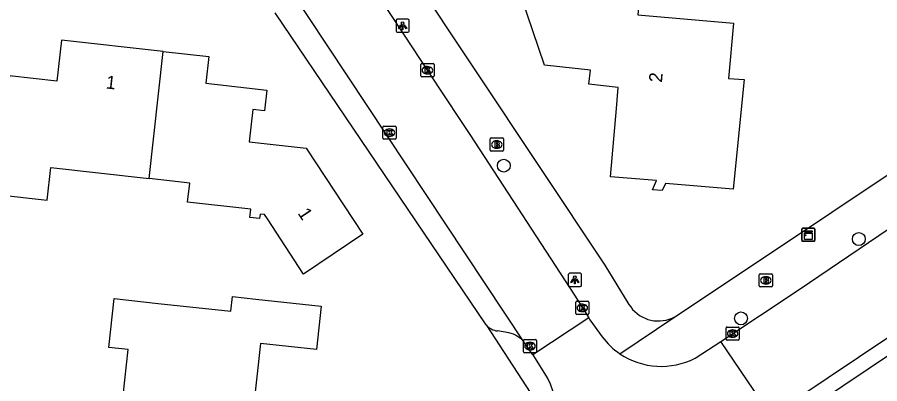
# Model space of a CAD drawing. Extents: x 162398 to 163643, y 386453 to 387397.
# Drawn here: x 163055.2 to 163120.8, y 386794.5 to 386822.3 of the extents above; entities that cross this region are included whole.
import ezdxf

# ---------------------------------------------------------------- set-up
doc = ezdxf.new("R2010")
doc.units = 0
for name, color, linetype in [('IMGEO_Boom', 7, 'Continuous'), ('IMGEO_Brandkraan', 7, 'Continuous'), ('IMGEO_Kast', 7, 'Continuous'), ('IMGEO_Kolk', 7, 'Continuous'), ('IMGEO_Lichtpunt', 7, 'Continuous'), ('IMGEO_Pand', 7, 'Continuous'), ('IMGEO_Pand_nummerreeks', 7, 'Continuous'), ('IMGEO_Parkeervlak_open', 7, 'Continuous'), ('IMGEO_Rijbaan_lokaal_gesloten', 7, 'Continuous'), ('IMGEO_Rijbaan_lokaal_open', 7, 'Continuous'), ('IMGEO_Voetpad_open', 7, 'Continuous')]:
    doc.layers.add(name, color=color, linetype=linetype)

msp = doc.modelspace()

# ---------------------------------------------------------------- linework, layer by layer
at = {"layer": 'IMGEO_Boom'}
for centre in [(163092.224, 386811.045), (163119.219, 386805.465), (163110.256, 386799.441)]:
    msp.add_circle(centre, 0.489, dxfattribs=at)
at = {"layer": 'IMGEO_Brandkraan'}
for p, q in [((163091.19, 386812.221), (163091.19, 386813.073)), ((163091.265, 386813.147), (163092.117, 386813.147)), ((163091.678, 386812.927), (163091.703, 386812.927)), ((163092.191, 386813.073), (163092.191, 386812.221)), ((163092.117, 386812.147), (163091.265, 386812.147)), ((163091.701, 386812.367), (163091.676, 386812.367)), ((163111.652, 386801.906), (163111.652, 386802.758)), ((163111.727, 386802.832), (163112.579, 386802.832)), ((163112.14, 386802.612), (163112.165, 386802.612)), ((163112.653, 386802.758), (163112.653, 386801.906)), ((163112.579, 386801.832), (163111.727, 386801.832)), ((163112.163, 386802.052), (163112.138, 386802.052))]:
    msp.add_line(p, q, dxfattribs=at)
for points in [[(163091.19, 386812.221), (163091.19, 386813.073)], [(163091.265, 386813.147), (163092.117, 386813.147)], [(163091.538, 386812.847), (163091.538, 386812.447), (163091.751, 386812.447)], [(163091.769, 386812.847), (163091.538, 386812.847)], [(163092.191, 386813.073), (163092.191, 386812.221)], [(163092.117, 386812.147), (163091.265, 386812.147)], [(163091.717, 386812.766), (163091.663, 386812.766), (163091.663, 386812.69)], [(163091.663, 386812.69), (163091.716, 386812.69)], [(163091.725, 386812.614), (163091.663, 386812.614), (163091.663, 386812.533)], [(163091.663, 386812.533), (163091.725, 386812.533)], [(163111.652, 386801.906), (163111.652, 386802.758)], [(163111.727, 386802.832), (163112.579, 386802.832)], [(163112, 386802.532), (163112, 386802.132), (163112.213, 386802.132)], [(163112.231, 386802.532), (163112, 386802.532)], [(163112.179, 386802.451), (163112.125, 386802.451), (163112.125, 386802.375)], [(163112.125, 386802.375), (163112.178, 386802.375)], [(163112.653, 386802.758), (163112.653, 386801.906)], [(163112.579, 386801.832), (163111.727, 386801.832)], [(163112.187, 386802.299), (163112.125, 386802.299), (163112.125, 386802.218)], [(163112.125, 386802.218), (163112.187, 386802.218)]]:
    msp.add_lwpolyline(points, dxfattribs=at)
for centre, radius, start, end in [((163091.267, 386813.071), 0.0765, 91.55205, 178.44795), ((163091.267, 386813.071), 0.0765, 91.55205, 178.44795), ((163091.773, 386812.702), 0.145, 59.4692, 91.53667), ((163091.798, 386812.749), 0.0922, 285.51372, 58.15012), ((163092.115, 386813.071), 0.0765, 1.55205, 88.44795), ((163092.115, 386813.071), 0.0765, 1.55205, 88.44795), ((163091.267, 386812.223), 0.0765, 181.55205, 268.44795), ((163091.267, 386812.223), 0.0765, 181.55205, 268.44795), ((163091.718, 386812.728), 0.0379, 267.82845, 90.93552), ((163091.726, 386812.573), 0.0404, 269.87594, 90.50774), ((163091.757, 386812.698), 0.251, 268.66757, 293.53466), ((163091.803, 386812.557), 0.105, 301.31148, 78.98903), ((163092.115, 386812.223), 0.0765, 271.55205, 358.44795), ((163092.115, 386812.223), 0.0765, 271.55205, 358.44795), ((163111.729, 386802.756), 0.0765, 91.55205, 178.44795), ((163111.729, 386802.756), 0.0765, 91.55205, 178.44795), ((163112.18, 386802.413), 0.0379, 267.82845, 90.93552), ((163112.235, 386802.387), 0.145, 59.4692, 91.53667), ((163112.26, 386802.434), 0.0922, 285.51372, 58.15012), ((163112.265, 386802.242), 0.105, 301.31148, 78.98903), ((163112.577, 386802.756), 0.0765, 1.55205, 88.44795), ((163112.577, 386802.756), 0.0765, 1.55205, 88.44795), ((163111.729, 386801.908), 0.0765, 181.55205, 268.44795), ((163111.729, 386801.908), 0.0765, 181.55205, 268.44795), ((163112.188, 386802.258), 0.0404, 269.87594, 90.50774), ((163112.219, 386802.383), 0.251, 268.66757, 293.53466), ((163112.577, 386801.908), 0.0765, 271.55205, 358.44795), ((163112.577, 386801.908), 0.0765, 271.55205, 358.44795)]:
    msp.add_arc(centre, radius, start, end, dxfattribs=at)
for centre, major_axis, ratio, start_param, end_param in [((163091.677, 386812.647), (-0.387, 0.002), 0.722429, 4.712389, 7.853982), ((163091.702, 386812.647), (-0.39, 0.002), 0.717154, 1.570796, 4.712389), ((163112.139, 386802.332), (-0.387, 0.002), 0.722429, 4.712389, 7.853982), ((163112.164, 386802.332), (-0.39, 0.002), 0.717154, 1.570796, 4.712389)]:
    msp.add_ellipse(centre, major_axis=major_axis, ratio=ratio, start_param=start_param, end_param=end_param, dxfattribs=at)
at = {"layer": 'IMGEO_Kast'}
for p, q in [((163114.961, 386806.297), (163115.802, 386806.297)), ((163115.802, 386806.297), (163114.961, 386806.297)), ((163114.886, 386805.372), (163114.886, 386806.213)), ((163114.886, 386806.213), (163114.886, 386805.372)), ((163115.886, 386806.222), (163115.886, 386805.381)), ((163115.886, 386805.381), (163115.886, 386806.222)), ((163115.811, 386805.297), (163114.97, 386805.297)), ((163114.97, 386805.297), (163115.811, 386805.297))]:
    msp.add_line(p, q, dxfattribs=at)
for points in [[(163115.081, 386806.087), (163115.681, 386806.087), (163115.681, 386806.002), (163115.081, 386806.002), (163115.081, 386806.087)], [(163115.081, 386805.912), (163115.681, 386805.912), (163115.681, 386805.423), (163115.081, 386805.423), (163115.081, 386805.912)]]:
    msp.add_lwpolyline(points, dxfattribs=at)
msp.add_circle((163115.165, 386805.761), 0.0377, dxfattribs=at)
for centre, start, end in [((163114.964, 386806.219), 92.4484, 184.28452), ((163114.964, 386806.219), 92.4484, 184.28452), ((163115.808, 386806.219), 2.4484, 94.28452), ((163115.808, 386806.219), 2.4484, 94.28452), ((163114.964, 386805.375), 182.4484, 274.28452), ((163114.964, 386805.375), 182.4484, 274.28452), ((163115.808, 386805.375), 272.4484, 4.28452), ((163115.808, 386805.375), 272.4484, 4.28452)]:
    msp.add_arc(centre, 0.0779, start, end, dxfattribs=at)
at = {"layer": 'IMGEO_Kolk'}
for p, q in [((163085.917, 386817.864), (163085.917, 386818.716)), ((163085.992, 386818.79), (163086.844, 386818.79)), ((163086.918, 386818.716), (163086.918, 386817.864)), ((163086.405, 386818.57), (163086.43, 386818.57)), ((163086.844, 386817.79), (163085.992, 386817.79)), ((163086.428, 386818.01), (163086.403, 386818.01)), ((163083.033, 386813.123), (163083.033, 386813.975)), ((163083.108, 386814.049), (163083.96, 386814.049)), ((163083.521, 386813.829), (163083.546, 386813.829)), ((163084.034, 386813.975), (163084.034, 386813.123)), ((163083.96, 386813.049), (163083.108, 386813.049)), ((163083.544, 386813.269), (163083.519, 386813.269)), ((163097.698, 386799.816), (163097.698, 386800.668)), ((163097.773, 386800.742), (163098.625, 386800.742)), ((163098.186, 386800.522), (163098.211, 386800.522)), ((163098.699, 386800.668), (163098.699, 386799.816)), ((163098.625, 386799.742), (163097.773, 386799.742)), ((163098.209, 386799.962), (163098.184, 386799.962)), ((163109.123, 386797.862), (163109.123, 386798.714)), ((163109.198, 386798.788), (163110.05, 386798.788)), ((163109.611, 386798.568), (163109.636, 386798.568)), ((163110.124, 386798.714), (163110.124, 386797.862)), ((163093.718, 386796.911), (163093.718, 386797.763)), ((163093.793, 386797.837), (163094.645, 386797.837)), ((163094.719, 386797.763), (163094.719, 386796.911)), ((163110.05, 386797.788), (163109.198, 386797.788)), ((163109.634, 386798.008), (163109.609, 386798.008)), ((163094.206, 386797.617), (163094.231, 386797.617)), ((163094.645, 386796.837), (163093.793, 386796.837)), ((163094.229, 386797.057), (163094.204, 386797.057))]:
    msp.add_line(p, q, dxfattribs=at)
for points in [[(163085.917, 386817.864), (163085.917, 386818.716)], [(163085.992, 386818.79), (163086.844, 386818.79)], [(163086.918, 386818.716), (163086.918, 386817.864)], [(163086.238, 386818.49), (163086.361, 386818.49), (163086.361, 386818.339), (163086.491, 386818.49), (163086.655, 386818.49), (163086.509, 386818.339), (163086.662, 386818.09), (163086.51, 386818.09), (163086.425, 386818.254), (163086.361, 386818.187), (163086.361, 386818.09), (163086.238, 386818.09), (163086.238, 386818.49)], [(163086.844, 386817.79), (163085.992, 386817.79)], [(163083.033, 386813.123), (163083.033, 386813.975)], [(163083.108, 386814.049), (163083.96, 386814.049)], [(163083.354, 386813.749), (163083.477, 386813.749), (163083.477, 386813.598), (163083.607, 386813.749), (163083.771, 386813.749), (163083.625, 386813.598), (163083.778, 386813.349), (163083.626, 386813.349), (163083.541, 386813.513), (163083.477, 386813.446), (163083.477, 386813.349), (163083.354, 386813.349), (163083.354, 386813.749)], [(163084.034, 386813.975), (163084.034, 386813.123)], [(163083.96, 386813.049), (163083.108, 386813.049)], [(163097.698, 386799.816), (163097.698, 386800.668)], [(163097.773, 386800.742), (163098.625, 386800.742)], [(163098.019, 386800.442), (163098.142, 386800.442), (163098.142, 386800.291), (163098.272, 386800.442), (163098.436, 386800.442), (163098.29, 386800.291), (163098.443, 386800.042), (163098.291, 386800.042), (163098.206, 386800.206), (163098.142, 386800.139), (163098.142, 386800.042), (163098.019, 386800.042), (163098.019, 386800.442)], [(163098.699, 386800.668), (163098.699, 386799.816)], [(163098.625, 386799.742), (163097.773, 386799.742)], [(163109.123, 386797.862), (163109.123, 386798.714)], [(163109.198, 386798.788), (163110.05, 386798.788)], [(163109.444, 386798.488), (163109.567, 386798.488), (163109.567, 386798.337), (163109.697, 386798.488), (163109.861, 386798.488), (163109.715, 386798.337), (163109.868, 386798.088), (163109.716, 386798.088), (163109.631, 386798.252), (163109.567, 386798.185), (163109.567, 386798.088), (163109.444, 386798.088), (163109.444, 386798.488)], [(163110.124, 386798.714), (163110.124, 386797.862)], [(163093.718, 386796.911), (163093.718, 386797.763)], [(163093.793, 386797.837), (163094.645, 386797.837)], [(163094.719, 386797.763), (163094.719, 386796.911)], [(163110.05, 386797.788), (163109.198, 386797.788)], [(163094.039, 386797.537), (163094.162, 386797.537), (163094.162, 386797.386), (163094.292, 386797.537), (163094.456, 386797.537), (163094.31, 386797.386), (163094.463, 386797.137), (163094.311, 386797.137), (163094.226, 386797.301), (163094.162, 386797.234), (163094.162, 386797.137), (163094.039, 386797.137), (163094.039, 386797.537)], [(163094.645, 386796.837), (163093.793, 386796.837)]]:
    msp.add_lwpolyline(points, dxfattribs=at)
for centre, start, end in [((163085.994, 386818.714), 91.55205, 178.44795), ((163085.994, 386818.714), 91.55205, 178.44795), ((163086.842, 386818.714), 1.55205, 88.44795), ((163086.842, 386818.714), 1.55205, 88.44795), ((163085.994, 386817.866), 181.55205, 268.44795), ((163085.994, 386817.866), 181.55205, 268.44795), ((163086.842, 386817.866), 271.55205, 358.44795), ((163086.842, 386817.866), 271.55205, 358.44795), ((163083.11, 386813.973), 91.55205, 178.44795), ((163083.11, 386813.973), 91.55205, 178.44795), ((163083.958, 386813.973), 1.55205, 88.44795), ((163083.958, 386813.973), 1.55205, 88.44795), ((163083.11, 386813.125), 181.55205, 268.44795), ((163083.11, 386813.125), 181.55205, 268.44795), ((163083.958, 386813.125), 271.55205, 358.44795), ((163083.958, 386813.125), 271.55205, 358.44795), ((163097.775, 386800.666), 91.55205, 178.44795), ((163097.775, 386800.666), 91.55205, 178.44795), ((163098.623, 386800.666), 1.55205, 88.44795), ((163098.623, 386800.666), 1.55205, 88.44795), ((163097.775, 386799.818), 181.55205, 268.44795), ((163097.775, 386799.818), 181.55205, 268.44795), ((163098.623, 386799.818), 271.55205, 358.44795), ((163098.623, 386799.818), 271.55205, 358.44795), ((163109.2, 386798.712), 91.55205, 178.44795), ((163109.2, 386798.712), 91.55205, 178.44795), ((163110.048, 386798.712), 1.55205, 88.44795), ((163110.048, 386798.712), 1.55205, 88.44795), ((163093.795, 386797.761), 91.55205, 178.44795), ((163093.795, 386797.761), 91.55205, 178.44795), ((163094.643, 386797.761), 1.55205, 88.44795), ((163094.643, 386797.761), 1.55205, 88.44795), ((163109.2, 386797.864), 181.55205, 268.44795), ((163109.2, 386797.864), 181.55205, 268.44795), ((163110.048, 386797.864), 271.55205, 358.44795), ((163110.048, 386797.864), 271.55205, 358.44795), ((163093.795, 386796.913), 181.55205, 268.44795), ((163093.795, 386796.913), 181.55205, 268.44795), ((163094.643, 386796.913), 271.55205, 358.44795), ((163094.643, 386796.913), 271.55205, 358.44795)]:
    msp.add_arc(centre, 0.0765, start, end, dxfattribs=at)
for centre, major_axis, ratio, start_param, end_param in [((163086.404, 386818.29), (-0.387, 0.002), 0.722429, 4.712389, 7.853982), ((163086.429, 386818.29), (-0.39, 0.002), 0.717154, 1.570796, 4.712389), ((163083.52, 386813.549), (-0.387, 0.002), 0.722429, 4.712389, 7.853982), ((163083.545, 386813.549), (-0.39, 0.002), 0.717154, 1.570796, 4.712389), ((163098.185, 386800.242), (-0.387, 0.002), 0.722429, 4.712389, 7.853982), ((163098.21, 386800.242), (-0.39, 0.002), 0.717154, 1.570796, 4.712389), ((163109.61, 386798.288), (-0.387, 0.002), 0.722429, 4.712389, 7.853982), ((163109.635, 386798.288), (-0.39, 0.002), 0.717154, 1.570796, 4.712389), ((163094.205, 386797.337), (-0.387, 0.002), 0.722429, 4.712389, 7.853982), ((163094.23, 386797.337), (-0.39, 0.002), 0.717154, 1.570796, 4.712389)]:
    msp.add_ellipse(centre, major_axis=major_axis, ratio=ratio, start_param=start_param, end_param=end_param, dxfattribs=at)
at = {"layer": 'IMGEO_Lichtpunt'}
for p, q in [((163084.031, 386822.069), (163084.031, 386821.262)), ((163084.031, 386822.069), (163084.031, 386821.262)), ((163084.933, 386822.164), (163084.125, 386822.164)), ((163084.933, 386822.164), (163084.125, 386822.164)), ((163085.027, 386821.262), (163085.027, 386822.069)), ((163085.027, 386821.262), (163085.027, 386822.069)), ((163084.125, 386821.168), (163084.933, 386821.168)), ((163084.125, 386821.168), (163084.933, 386821.168)), ((163097.131, 386802.773), (163097.131, 386801.966)), ((163097.131, 386802.773), (163097.131, 386801.966)), ((163098.033, 386802.868), (163097.225, 386802.868)), ((163098.033, 386802.868), (163097.225, 386802.868)), ((163098.127, 386801.966), (163098.127, 386802.773)), ((163098.127, 386801.966), (163098.127, 386802.773)), ((163097.225, 386801.872), (163098.033, 386801.872)), ((163097.225, 386801.872), (163098.033, 386801.872))]:
    msp.add_line(p, q, dxfattribs=at)
for points in [[(163084.405, 386821.733), (163084.444, 386821.705), (163084.256, 386821.443), (163084.218, 386821.47), (163084.405, 386821.733)], [(163084.507, 386821.685), (163084.554, 386821.685), (163084.554, 386821.363), (163084.507, 386821.363), (163084.507, 386821.685)], [(163084.617, 386821.705), (163084.655, 386821.732), (163084.842, 386821.47), (163084.803, 386821.442), (163084.617, 386821.705)], [(163097.505, 386802.437), (163097.544, 386802.409), (163097.356, 386802.147), (163097.318, 386802.174), (163097.505, 386802.437)], [(163097.607, 386802.389), (163097.654, 386802.389), (163097.654, 386802.067), (163097.607, 386802.067), (163097.607, 386802.389)], [(163097.717, 386802.409), (163097.755, 386802.436), (163097.942, 386802.174), (163097.903, 386802.146), (163097.717, 386802.409)]]:
    msp.add_lwpolyline(points, dxfattribs=at)
for centre in [(163084.53, 386821.867), (163097.63, 386802.571)]:
    msp.add_circle(centre, 0.0994, dxfattribs=at)
for centre, start, end in [((163084.125, 386822.069), 90, 180), ((163084.125, 386822.069), 90, 180), ((163084.933, 386822.069), 0, 90), ((163084.933, 386822.069), 0, 90), ((163084.125, 386821.262), 180, 270), ((163084.125, 386821.262), 180, 270), ((163084.933, 386821.262), 270, 0), ((163084.933, 386821.262), 270, 360), ((163097.225, 386802.773), 90, 180), ((163097.225, 386802.773), 90, 180), ((163098.033, 386802.773), 0, 90), ((163098.033, 386802.773), 0, 90), ((163097.225, 386801.966), 180, 270), ((163097.225, 386801.966), 180, 270), ((163098.033, 386801.966), 270, 0), ((163098.033, 386801.966), 270, 360)]:
    msp.add_arc(centre, 0.0946, start, end, dxfattribs=at)
at = {"layer": 'IMGEO_Pand'}
for points in [[(163101.8, 386825.576), (163102.676, 386825.5), (163102.414, 386822.492), (163109.685, 386821.858), (163109.32, 386817.672), (163110.501, 386817.598), (163109.668, 386809.251), (163104.521, 386809.7), (163104.262, 386809.153), (163103.522, 386809.218), (163103.835, 386809.928), (163100.333, 386810.201), (163100.785, 386815.382), (163100.923, 386816.971), (163098.696, 386817.239), (163098.807, 386818.304), (163095.318, 386818.67), (163092.713, 386826.368), (163098.293, 386825.882)], [(163066.327, 386819.722), (163058.593, 386820.582), (163058.245, 386817.455), (163054.632, 386817.856), (163054.132, 386813.363), (163053.632, 386808.864), (163057.516, 386808.432), (163057.789, 386810.893), (163065.254, 386810.063)], [(163065.254, 386810.063), (163066.327, 386819.722)], [(163066.327, 386819.722), (163069.802, 386819.335), (163069.575, 386817.3), (163074.213, 386816.784), (163074.037, 386815.205), (163073.141, 386815.305), (163072.867, 386812.843), (163077.194, 386812.362), (163081.496, 386805.85), (163076.99, 386802.809), (163074.251, 386806.993), (163074.029, 386807.331), (163073.692, 386807.369), (163073.654, 386807.022), (163072.91, 386807.104), (163072.981, 386807.748), (163068.183, 386808.281), (163068.343, 386809.719), (163065.254, 386810.063)], [(163062.9, 386790.106), (163063.658, 386797.073), (163062.183, 386797.234), (163062.587, 386800.949), (163065.941, 386800.584), (163071.468, 386799.982), (163071.59, 386801.104), (163073.363, 386800.911), (163078.333, 386800.37), (163077.975, 386797.081), (163073.726, 386797.543), (163072.8, 386789.031)]]:
    msp.add_lwpolyline(points, dxfattribs=at)
at = {"layer": 'IMGEO_Parkeervlak_open'}
msp.add_lwpolyline([(163090.874, 386798.95), (163074.837, 386822.643)], dxfattribs=at)
at = {"layer": 'IMGEO_Rijbaan_lokaal_gesloten'}
for points in [[(163108.718, 386797.688), (163114.688, 386801.643), (163126.014, 386809.308), (163142.367, 386820.061), (163142.553, 386820.191)], [(163128.699, 386802.855), (163128.182, 386802.509), (163114.647, 386793.426), (163112.536, 386792.008)]]:
    msp.add_lwpolyline(points, dxfattribs=at)
at = {"layer": 'IMGEO_Rijbaan_lokaal_open'}
for points in [[(163045.549, 386876.981), (163048.719, 386873.794), (163051.94, 386869.963), (163054.925, 386865.823), (163055.939, 386864.293), (163058.066, 386861.082), (163070.601, 386842.162), (163072.682, 386839.022), (163084.661, 386820.941), (163086.459, 386818.227), (163088.943, 386814.478), (163089.654, 386813.404), (163097.59, 386801.208), (163098.684, 386799.487)], [(163093.805, 386797.593), (163074.36, 386826.913)], [(163098.684, 386799.487), (163094.437, 386796.681)], [(163098.684, 386799.487), (163098.774, 386799.346), (163099.704, 386798.039)], [(163094.437, 386796.681), (163093.805, 386797.593)], [(163106.767, 386796.421), (163108.718, 386797.688)], [(163111.717, 386793.28), (163108.718, 386797.688)], [(163095.547, 386794.922), (163094.499, 386796.592), (163094.437, 386796.681)]]:
    msp.add_lwpolyline(points, dxfattribs=at)
for centre, radius, start, end in [((163104.198, 386801.429), 5.629, 217.0304, 236.06121), ((163104.198, 386801.432), 5.631, 236.08046, 297.14664), ((163090.757, 386792.349), 5.437, 301.52199, 28.24641)]:
    msp.add_arc(centre, radius, start, end, dxfattribs=at)
at = {"layer": 'IMGEO_Voetpad_open'}
for points in [[(163055.371, 386870.345), (163099.918, 386803.497), (163101.741, 386800.505), (163101.872, 386800.31), (163102.019, 386800.128), (163102.182, 386799.96), (163102.36, 386799.807), (163102.551, 386799.671), (163102.753, 386799.552), (163102.964, 386799.452), (163103.184, 386799.371), (163103.411, 386799.309), (163103.641, 386799.269), (163103.875, 386799.249), (163104.109, 386799.25), (163104.343, 386799.272), (163104.573, 386799.315), (163104.799, 386799.378), (163105.018, 386799.461), (163105.229, 386799.564)], [(163105.229, 386799.564), (163105.43, 386799.684), (163105.441, 386799.692), (163140.645, 386823.163)], [(163146.898, 386813.664), (163065.982, 386759.453)], [(163101.055, 386796.759), (163105.229, 386799.564)], [(163090.874, 386798.95), (163094.938, 386792.726), (163030.691, 386750), (163014.944, 386739.528)], [(163092.612, 386798.353), (163091.754, 386798.487)]]:
    msp.add_lwpolyline(points, dxfattribs=at)
for centre, radius, start, end in [((163091.956, 386799.938), 1.465, 222.40848, 262.09054), ((163092.123, 386796.269), 2.141, 38.21281, 76.78888)]:
    msp.add_arc(centre, radius, start, end, dxfattribs=at)

# ---------------------------------------------------------------- texts
at = {"layer": 'IMGEO_Pand_nummerreeks'}
for s, rotation, p in [('2', 85.02121, (163104.248, 386817.333)), ('1', 353.6459, (163061.936, 386816.909)), ('1', 303.44981, (163076.519, 386807.433))]:
    msp.add_text(s, height=1, rotation=rotation, dxfattribs=at).set_placement(p)

doc.saveas('drawing.dxf')
